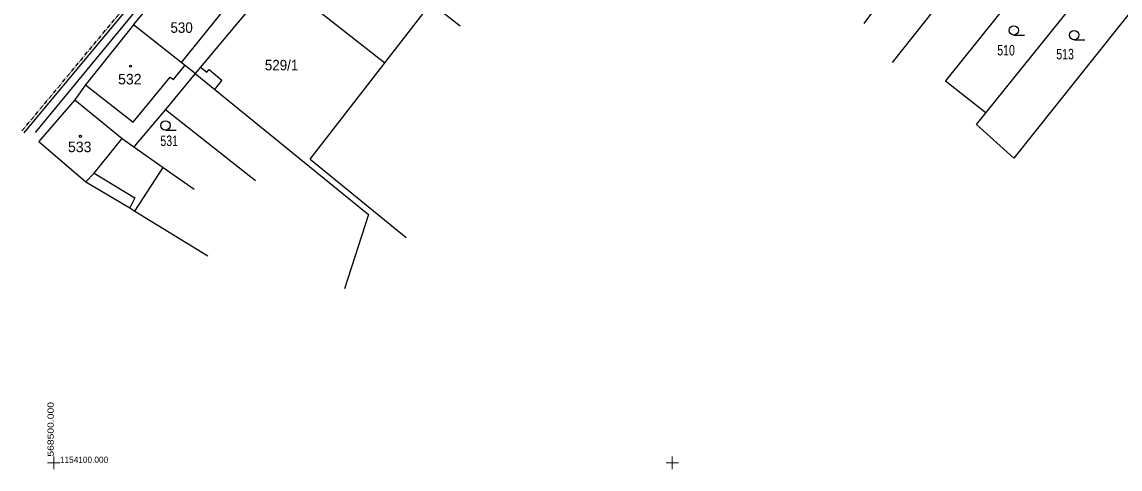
# Model space of a CAD drawing. Extents: x -568530 to -568223, y -1154101 to -1153740.
# Drawn here: x -568505.1 to -568327.6, y -1154101 to -1154028.8 of the extents above; entities that cross this region are included whole.
import ezdxf

# ---------------------------------------------------------------- set-up
doc = ezdxf.new("R2010")
doc.units = 0
doc.header["$LTSCALE"] = 0.14
doc.linetypes.add('DOT_DASHED', pattern=[7.7, 5, -1.2, 0.3, -1.2])
for name, color, linetype, lineweight in [('1', 7, 'Continuous', 25), ('25', 7, 'Continuous', 13), ('4', 7, 'Continuous', 25), ('6', 7, 'DOT_DASHED', 25), ('61', 7, 'Continuous', 13)]:
    doc.layers.add(name, color=color, linetype=linetype, lineweight=lineweight)
doc.layers.add('18', color=7, linetype='Continuous')
doc.layers.add('19', color=7, linetype='Continuous')

msp = doc.modelspace()

# ---------------------------------------------------------------- linework, layer by layer
at = {"layer": '1'}
for p, q in [((-568336.76, -1154000.54), (-568364.47, -1154035.32)), ((-568329.89, -1154005.8), (-568355.84, -1154038.27)), ((-568350.83, -1154045.34), (-568323.15, -1154010.95)), ((-568474.11, -1154013.58), (-568446.48, -1154035.38)), ((-568365.23, -1154023.86), (-568369.04, -1154029.03)), ((-568355.84, -1154038.27), (-568349.28, -1154043.42)), ((-568458.52, -1154050.91), (-568443.03, -1154063.6)), ((-568486.89, -1154059.35), (-568475.09, -1154066.57))]:
    msp.add_line(p, q, dxfattribs=at)
for points in [[(-568466.1, -1154002.33), (-568467.98, -1154002.62), (-568469.45, -1154004.08), (-568470.88, -1154005.77), (-568469.89, -1154006.46), (-568485.53, -1154025.47), (-568502.98, -1154046.64)], [(-568504.75, -1154046.69), (-568477.59, -1154014.04), (-568470.88, -1154005.77)], [(-568317.63, -1154016.68), (-568344.8, -1154050.79), (-568350.83, -1154045.34)], [(-568458.52, -1154050.91), (-568438.98, -1154025.71), (-568434.27, -1154029.4)], [(-568487.09, -1154029.21), (-568494.88, -1154038.94), (-568496.58, -1154041.37), (-568502.41, -1154048.08)], [(-568477.14, -1154037.09), (-568449.12, -1154059.89), (-568452.97, -1154071.86)], [(-568496.58, -1154041.37), (-568488.93, -1154047.58), (-568487.04, -1154048.93), (-568482.32, -1154052.3), (-568477.3, -1154055.8)], [(-568502.41, -1154048.08), (-568494.79, -1154054.58), (-568487.67, -1154058.81), (-568486.89, -1154059.35), (-568482.32, -1154052.3)]]:
    msp.add_lwpolyline(points, dxfattribs=at)
msp.add_lwpolyline([(-568478.42, -1154018.84), (-568468.49, -1154026.81), (-568477.14, -1154037.09), (-568487.09, -1154029.21)], close=True, dxfattribs=at)
at = {"layer": '25', "lineweight": 25}
for p, q in [((-568344.79, -1154030.87), (-568343.04, -1154030.87)), ((-568335.03, -1154031.64), (-568333.28, -1154031.64)), ((-568481.94, -1154046.23), (-568480.19, -1154046.23))]:
    msp.add_line(p, q, dxfattribs=at)
for centre, radius in [((-568344.79, -1154030.12), 0.75), ((-568335.03, -1154030.89), 0.75), ((-568487.58, -1154035.91), 0.175), ((-568481.94, -1154045.48), 0.75), ((-568495.68, -1154047.25), 0.175)]:
    msp.add_circle(centre, radius, dxfattribs=at)
at = {"layer": '4'}
for p, q in [((-568479.36, -1154035.33), (-568470.92, -1154024.86)), ((-568481.9, -1154042.9), (-568487.04, -1154048.93)), ((-568494.79, -1154054.58), (-568493.44, -1154053.19)), ((-568486.87, -1154057.19), (-568487.67, -1154058.81))]:
    msp.add_line(p, q, dxfattribs=at)
for points in [[(-568494.88, -1154038.94), (-568487.14, -1154044.94), (-568481.19, -1154037.67), (-568480.61, -1154038.07), (-568478.78, -1154035.79)], [(-568476.26, -1154036.04), (-568475.24, -1154036.86), (-568474.87, -1154036.46), (-568472.8, -1154038.17), (-568473.98, -1154039.66)], [(-568477.14, -1154037.09), (-568481.9, -1154042.9), (-568467.4, -1154054.37)], [(-568493.44, -1154053.19), (-568488.93, -1154047.58), (-568487.04, -1154048.93), (-568482.32, -1154052.3)], [(-568494.79, -1154054.58), (-568493.44, -1154053.19), (-568486.87, -1154057.19)]]:
    msp.add_lwpolyline(points, dxfattribs=at)
at = {"layer": '6'}
msp.add_line((-568505.13, -1154046.37), (-568477.97, -1154013.72), dxfattribs=at)
at = {"layer": '61'}
for p, q in [((-568501, -1154100), (-568499, -1154100)), ((-568500, -1154099), (-568500, -1154101)), ((-568401, -1154100), (-568399, -1154100)), ((-568400, -1154099), (-568400, -1154101))]:
    msp.add_line(p, q, dxfattribs=at)

# ---------------------------------------------------------------- texts
at = {"layer": '18'}
for s, width, p in [('510', 0.75, (-568347.46, -1154034.17)), ('529/1', 0.95, (-568465.86, -1154036.58)), ('513', 0.75, (-568337.92, -1154034.81)), ('531', 0.75, (-568482.75, -1154048.81))]:
    msp.add_text(s, height=1.7, dxfattribs=dict(at, width=width)).set_placement(p)
at = {"layer": '19', "width": 0.95}
msp.add_text('530', height=1.7, dxfattribs=at).set_placement((-568481.12, -1154030.52))
at = {"layer": '19'}
for s, p in [('532', (-568489.59, -1154038.85)), ('533', (-568497.69, -1154049.8))]:
    msp.add_text(s, height=1.7, dxfattribs=at).set_placement(p)
at = {"layer": '61', "width": 1.25}
msp.add_text('568500.000', height=1, rotation=90, dxfattribs=at).set_placement((-568500, -1154099))
at = {"layer": '61'}
msp.add_text('1154100.000', height=1, dxfattribs=at).set_placement((-568499, -1154100))

doc.saveas('drawing.dxf')
